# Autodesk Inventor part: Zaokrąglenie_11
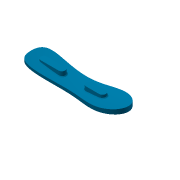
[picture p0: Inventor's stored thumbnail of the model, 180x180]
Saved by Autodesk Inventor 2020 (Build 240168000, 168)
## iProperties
Created: 2006-08
Part Number: Zaokrąglenie_11
Document SubType Name: Modeling
Designer: F.Stasiak
Density: 1 g/cm^3
Material: Ogólny
Appearance: Średniobłękitna
Manager: www.cadconsulting.pl
Company: Fabian Stasiak CAD Consulting
Author: F.Stasiak
Subject: Zbiór ćwiczeń. Autodesk Inventor 2020. Kurs podstawowy
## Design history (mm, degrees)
feature "Baza1"
node "Bryła1"
node "Korpusy bryłowe"
node "Korpusy powierzchniowe"
